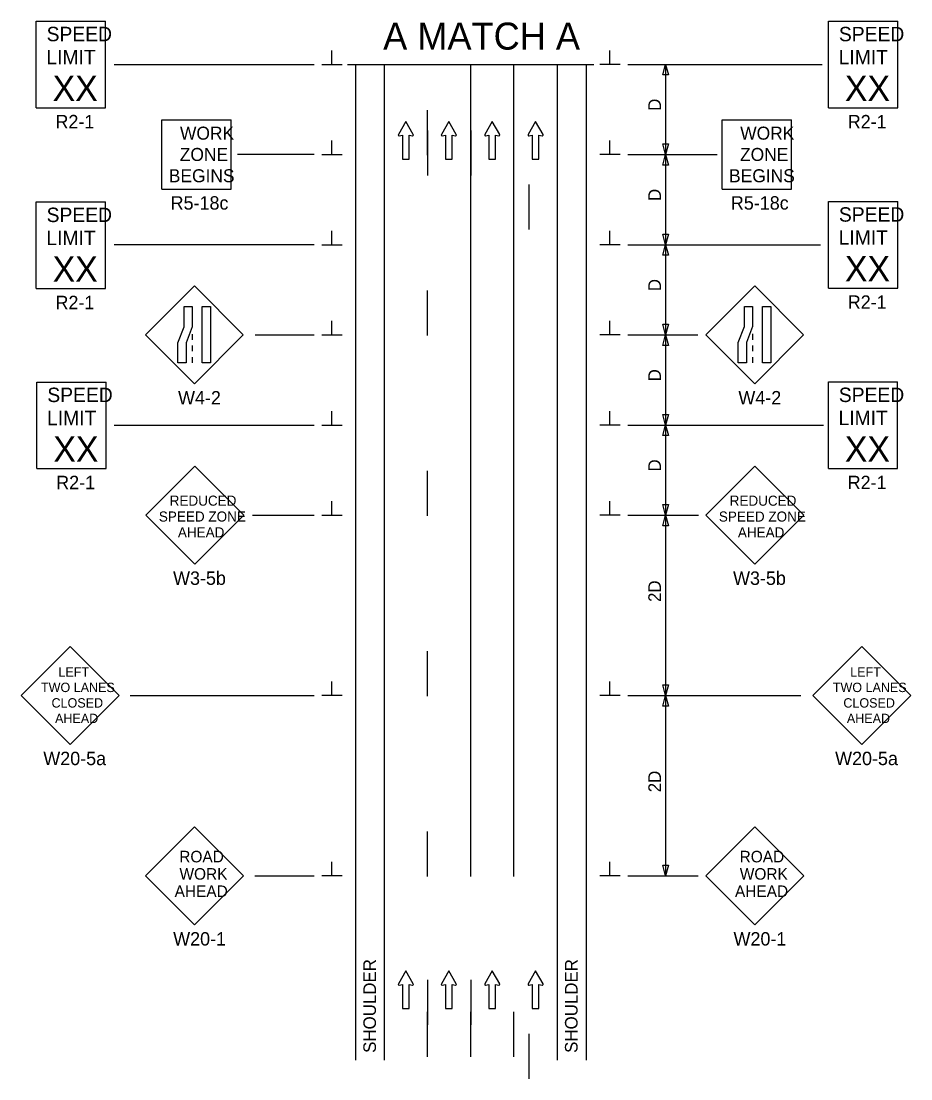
# Model space of a CAD drawing. Extents: x 16519 to 19508, y 5743 to 6974.
# Drawn here: x 17852 to 18345, y 6327 to 6913 of the extents above; entities that cross this region are included whole.
import ezdxf

# ---------------------------------------------------------------- set-up
doc = ezdxf.new("R2010")
doc.units = 0
for name, color, linetype in [('ALI_LEGAL_EX', 7, 'Continuous'), ('MT_SCRATCH_LEVEL_E', 7, 'Continuous'), ('PAVT_EDGE_EX', 7, 'Continuous'), ('TRAFFIC_SIGNS_PR', 7, 'Continuous'), ('TYPICAL_TEXT_DIMEN_PR', 7, 'Continuous')]:
    doc.layers.add(name, color=color, linetype=linetype)

msp = doc.modelspace()

# ---------------------------------------------------------------- linework, layer by layer
at = {"layer": 'ALI_LEGAL_EX'}
for p, q in [((18101.18, 6438.7), (18101.18, 6889.05)), ((18125.18, 6438.7), (18125.18, 6889.05))]:
    msp.add_line(p, q, dxfattribs=at)
for points in [[(18077.18, 6838.7), (18077.18, 6863.7)], [(18101.18, 6838.7), (18101.18, 6863.7)], [(18125.18, 6838.7), (18125.18, 6863.7)], [(18077.28, 6852.4), (18077.28, 6827.4)], [(18101.28, 6852.4), (18101.28, 6827.4)], [(18133.42, 6822.52), (18133.42, 6797.52)], [(18077.18, 6738.7), (18077.18, 6763.7)], [(18101.18, 6738.7), (18101.18, 6763.7)], [(18125.18, 6738.7), (18125.18, 6763.7)], [(18077.18, 6638.7), (18077.18, 6663.7)], [(18101.18, 6638.7), (18101.18, 6663.7)], [(18125.18, 6638.7), (18125.18, 6663.7)], [(18077.18, 6538.7), (18077.18, 6563.7)], [(18101.18, 6538.7), (18101.18, 6563.7)], [(18125.18, 6538.7), (18125.18, 6563.7)], [(18077.18, 6438.7), (18077.18, 6463.7)], [(18101.18, 6438.7), (18101.18, 6463.7)], [(18125.18, 6438.7), (18125.18, 6463.7)], [(18077.28, 6381.39), (18077.28, 6356.39)], [(18101.28, 6381.39), (18101.28, 6356.39)], [(18077.18, 6338.7), (18077.18, 6363.7)], [(18101.18, 6338.7), (18101.18, 6363.7)], [(18125.18, 6338.7), (18125.18, 6363.7)], [(18133.42, 6351.51), (18133.42, 6326.51)]]:
    msp.add_lwpolyline(points, dxfattribs=at)
at = {"layer": 'MT_SCRATCH_LEVEL_E'}
for p, q in [((18065.19, 6857.36), (18061.08, 6850.12)), ((18069.34, 6850.12), (18065.19, 6857.36)), ((18089.05, 6857.36), (18084.94, 6850.12)), ((18093.19, 6850.12), (18089.05, 6857.36)), ((18113.1, 6857.36), (18108.99, 6850.12)), ((18117.25, 6850.12), (18113.1, 6857.36)), ((18137.15, 6857.36), (18133.04, 6850.12)), ((18137.15, 6857.36), (18133.04, 6850.12)), ((18141.3, 6850.12), (18137.15, 6857.36)), ((18141.3, 6850.12), (18137.15, 6857.36)), ((18061.57, 6849.44), (18063.34, 6849.75)), ((18063.34, 6849.75), (18063.34, 6836.5)), ((18067.08, 6836.5), (18067.08, 6849.75)), ((18067.08, 6849.75), (18068.86, 6849.44)), ((18085.42, 6849.44), (18087.19, 6849.75)), ((18087.19, 6849.75), (18087.19, 6836.5)), ((18090.94, 6836.5), (18090.94, 6849.75)), ((18090.94, 6849.75), (18092.71, 6849.44)), ((18109.47, 6849.44), (18111.25, 6849.75)), ((18111.25, 6849.75), (18111.25, 6836.5)), ((18114.99, 6836.5), (18114.99, 6849.75)), ((18114.99, 6849.75), (18116.77, 6849.44)), ((18133.52, 6849.44), (18135.3, 6849.76)), ((18133.52, 6849.44), (18135.3, 6849.76)), ((18135.3, 6849.76), (18135.3, 6836.5)), ((18135.3, 6849.76), (18135.3, 6836.5)), ((18139.04, 6836.5), (18139.04, 6849.76)), ((18139.04, 6849.76), (18140.82, 6849.44)), ((18139.04, 6836.5), (18139.04, 6849.76)), ((18139.04, 6849.76), (18140.82, 6849.44)), ((18063.34, 6836.5), (18067.08, 6836.5)), ((18087.19, 6836.5), (18090.94, 6836.5)), ((18111.25, 6836.5), (18114.99, 6836.5)), ((18135.3, 6836.5), (18139.04, 6836.5)), ((18135.3, 6836.5), (18139.04, 6836.5)), ((18065.19, 6386.35), (18061.08, 6379.11)), ((18069.34, 6379.11), (18065.19, 6386.35)), ((18089.05, 6386.35), (18084.94, 6379.11)), ((18093.19, 6379.11), (18089.05, 6386.35)), ((18113.1, 6386.35), (18108.99, 6379.11)), ((18117.25, 6379.11), (18113.1, 6386.35)), ((18137.15, 6386.35), (18133.04, 6379.11)), ((18137.15, 6386.35), (18133.04, 6379.11)), ((18141.3, 6379.11), (18137.15, 6386.35)), ((18141.3, 6379.11), (18137.15, 6386.35)), ((18061.57, 6378.43), (18063.34, 6378.74)), ((18063.34, 6378.74), (18063.34, 6365.49)), ((18067.08, 6365.49), (18067.08, 6378.74)), ((18067.08, 6378.74), (18068.86, 6378.43)), ((18085.42, 6378.43), (18087.19, 6378.74)), ((18087.19, 6378.74), (18087.19, 6365.49)), ((18090.94, 6365.49), (18090.94, 6378.74)), ((18090.94, 6378.74), (18092.71, 6378.43)), ((18109.47, 6378.43), (18111.25, 6378.74)), ((18111.25, 6378.74), (18111.25, 6365.49)), ((18114.99, 6365.49), (18114.99, 6378.74)), ((18114.99, 6378.74), (18116.77, 6378.43)), ((18133.52, 6378.43), (18135.3, 6378.74)), ((18133.52, 6378.43), (18135.3, 6378.74)), ((18135.3, 6378.74), (18135.3, 6365.49)), ((18135.3, 6378.74), (18135.3, 6365.49)), ((18139.04, 6365.49), (18139.04, 6378.74)), ((18139.04, 6378.74), (18140.82, 6378.43)), ((18139.04, 6365.49), (18139.04, 6378.74)), ((18139.04, 6378.74), (18140.82, 6378.43)), ((18063.34, 6365.49), (18067.08, 6365.49)), ((18087.19, 6365.49), (18090.94, 6365.49)), ((18111.25, 6365.49), (18114.99, 6365.49)), ((18135.3, 6365.49), (18139.04, 6365.49)), ((18135.3, 6365.49), (18139.04, 6365.49))]:
    msp.add_line(p, q, dxfattribs=at)
for centre, start, end in [((18061.49, 6849.9), 150.42484, 279.96381), ((18068.93, 6849.9), 260.03619, 29.77312), ((18085.34, 6849.9), 150.42484, 279.96381), ((18092.78, 6849.9), 260.03619, 29.77312), ((18109.4, 6849.9), 150.42484, 279.96381), ((18116.84, 6849.9), 260.03619, 29.77312), ((18133.45, 6849.9), 150.42484, 279.96381), ((18133.45, 6849.9), 150.42484, 279.96381), ((18140.89, 6849.9), 260.03619, 29.77312), ((18140.89, 6849.9), 260.03619, 29.77312), ((18061.49, 6378.89), 150.42484, 279.96381), ((18068.93, 6378.89), 260.03619, 29.77312), ((18085.34, 6378.89), 150.42484, 279.96381), ((18092.78, 6378.89), 260.03619, 29.77312), ((18109.4, 6378.89), 150.42484, 279.96381), ((18116.84, 6378.89), 260.03619, 29.77312), ((18133.45, 6378.89), 150.42484, 279.96381), ((18133.45, 6378.89), 150.42484, 279.96381), ((18140.89, 6378.89), 260.03619, 29.77312), ((18140.89, 6378.89), 260.03619, 29.77312)]:
    msp.add_arc(centre, 0.463, start, end, dxfattribs=at)
at = {"layer": 'PAVT_EDGE_EX'}
for p, q in [((18037.18, 6889.05), (18037.18, 6336.88)), ((18053.18, 6889.05), (18053.18, 6336.88)), ((18149.18, 6889.05), (18149.18, 6336.88)), ((18165.18, 6889.05), (18165.18, 6336.88))]:
    msp.add_line(p, q, dxfattribs=at)
at = {"layer": 'TRAFFIC_SIGNS_PR'}
for p, q in [((17860.13, 6913.02), (17898.53, 6913.02)), ((17860.13, 6865.02), (17860.13, 6913.02)), ((17898.53, 6865.02), (17898.53, 6913.02)), ((18299.69, 6913), (18338.09, 6913)), ((18299.69, 6865), (18299.69, 6913)), ((18338.09, 6865), (18338.09, 6913)), ((17860.13, 6865.02), (17898.53, 6865.02)), ((18299.69, 6865), (18338.09, 6865)), ((17929.89, 6819.94), (17929.89, 6858.34)), ((17929.89, 6858.34), (17968.29, 6858.34)), ((17968.29, 6819.94), (17968.29, 6858.34)), ((18240.71, 6819.94), (18240.71, 6858.34)), ((18240.71, 6858.34), (18279.11, 6858.34)), ((18279.11, 6819.94), (18279.11, 6858.34)), ((17929.89, 6819.94), (17968.29, 6819.94)), ((18240.71, 6819.94), (18279.11, 6819.94)), ((17860.13, 6812.74), (17898.53, 6812.74)), ((17860.13, 6764.74), (17860.13, 6812.74)), ((17898.53, 6764.74), (17898.53, 6812.74)), ((18299.69, 6812.96), (18338.09, 6812.96)), ((18299.69, 6764.96), (18299.69, 6812.96)), ((18338.09, 6764.96), (18338.09, 6812.96)), ((17860.13, 6764.74), (17898.53, 6764.74)), ((17947.86, 6766.19), (17920.71, 6739.04)), ((17975.01, 6739.04), (17947.86, 6766.19)), ((18258.74, 6766.22), (18231.58, 6739.07)), ((18285.89, 6739.07), (18258.74, 6766.22)), ((18299.69, 6764.96), (18338.09, 6764.96)), ((17920.71, 6739.04), (17947.86, 6711.89)), ((17946.61, 6739.53), (17946.61, 6736.33)), ((17947.86, 6711.89), (17975.01, 6739.04)), ((18231.58, 6739.07), (18258.74, 6711.92)), ((18257.49, 6739.56), (18257.49, 6736.36)), ((18258.74, 6711.92), (18285.89, 6739.07)), ((18257.49, 6733.16), (18257.49, 6729.96)), ((17946.61, 6733.13), (17946.61, 6729.93)), ((17946.61, 6726.73), (17946.61, 6723.53)), ((18257.49, 6726.76), (18257.49, 6723.56)), ((17860.53, 6712.92), (17898.93, 6712.92)), ((17860.53, 6664.92), (17860.53, 6712.92)), ((17898.93, 6664.92), (17898.93, 6712.92)), ((18299.65, 6712.95), (18338.05, 6712.95)), ((18299.65, 6664.95), (18299.65, 6712.95)), ((18338.05, 6664.95), (18338.05, 6712.95)), ((17860.53, 6664.92), (17898.93, 6664.92)), ((17948.12, 6666.17), (17920.97, 6639.02)), ((17975.27, 6639.02), (17948.12, 6666.17)), ((18258.8, 6666.16), (18231.65, 6639.01)), ((18285.95, 6639.01), (18258.8, 6666.16)), ((18299.65, 6664.95), (18338.05, 6664.95)), ((17920.97, 6639.02), (17948.12, 6611.87)), ((17948.12, 6611.87), (17975.27, 6639.02)), ((18231.65, 6639.01), (18258.8, 6611.85)), ((18258.8, 6611.85), (18285.95, 6639.01)), ((17878.92, 6566.2), (17851.76, 6539.05)), ((17906.07, 6539.05), (17878.92, 6566.2)), ((18318.22, 6566.2), (18291.07, 6539.05)), ((18345.38, 6539.05), (18318.22, 6566.2)), ((17851.76, 6539.05), (17878.92, 6511.9)), ((17878.92, 6511.9), (17906.07, 6539.05)), ((18291.07, 6539.05), (18318.22, 6511.9)), ((18318.22, 6511.9), (18345.38, 6539.05)), ((17947.95, 6466.17), (17920.8, 6439.01)), ((17975.1, 6439.01), (17947.95, 6466.17)), ((18258.83, 6466.17), (18231.67, 6439.01)), ((18285.98, 6439.01), (18258.83, 6466.17)), ((17920.8, 6439.01), (17947.95, 6411.86)), ((17947.95, 6411.86), (17975.1, 6439.01)), ((18231.67, 6439.01), (18258.83, 6411.86)), ((18258.83, 6411.86), (18285.98, 6439.01))]:
    msp.add_line(p, q, dxfattribs=at)
for points in [[(17946.61, 6754.78), (17946.61, 6743.6), (17943.27, 6734.71), (17943.27, 6723.53), (17938.77, 6723.53), (17938.77, 6734.71), (17942.12, 6743.6), (17942.12, 6754.78)], [(17956.75, 6754.78), (17956.75, 6723.53), (17952.25, 6723.53), (17952.25, 6754.78)], [(18257.49, 6754.81), (18257.49, 6743.63), (18254.14, 6734.74), (18254.14, 6723.56), (18249.65, 6723.56), (18249.65, 6734.74), (18252.99, 6743.63), (18252.99, 6754.81)], [(18267.62, 6754.81), (18267.62, 6723.56), (18263.13, 6723.56), (18263.13, 6754.81)]]:
    msp.add_lwpolyline(points, close=True, dxfattribs=at)
at = {"layer": 'TYPICAL_TEXT_DIMEN_PR'}
for p, q in [((18024.15, 6889.05), (18024.15, 6896.83)), ((18178.4, 6889.05), (18178.4, 6896.83)), ((17903.38, 6889.05), (18014.28, 6889.05)), ((18018.53, 6889.05), (18029.78, 6889.05)), ((18032.85, 6889.05), (18169.5, 6889.05)), ((18184.03, 6889.05), (18172.78, 6889.05)), ((18188.28, 6889.05), (18296.09, 6889.05)), ((18207.71, 6883.19), (18209.28, 6889.05)), ((18209.28, 6889.05), (18209.28, 6839.05)), ((18209.28, 6889.05), (18210.85, 6883.19)), ((18209.28, 6883.19), (18207.71, 6883.19)), ((18210.85, 6883.19), (18209.28, 6883.19)), ((18024.15, 6839.05), (18024.15, 6846.83)), ((18178.4, 6839.05), (18178.4, 6846.83)), ((18209.28, 6839.05), (18207.71, 6844.91)), ((18207.71, 6844.91), (18209.28, 6844.91)), ((18209.28, 6844.91), (18210.85, 6844.91)), ((18210.85, 6844.91), (18209.28, 6839.05)), ((18014.28, 6839.05), (17971.89, 6839.05)), ((18018.53, 6839.05), (18029.78, 6839.05)), ((18184.03, 6839.05), (18172.78, 6839.05)), ((18188.28, 6839.05), (18237.93, 6839.05)), ((18207.71, 6833.19), (18209.28, 6839.05)), ((18209.28, 6839.05), (18210.85, 6833.19)), ((18209.28, 6839.05), (18209.28, 6789.05)), ((18209.28, 6833.19), (18207.71, 6833.19)), ((18210.85, 6833.19), (18209.28, 6833.19)), ((18024.15, 6789.05), (18024.15, 6796.83)), ((18178.4, 6789.05), (18178.4, 6796.83)), ((18209.28, 6789.05), (18207.71, 6794.91)), ((18207.71, 6794.91), (18209.28, 6794.91)), ((18209.28, 6794.91), (18210.85, 6794.91)), ((18210.85, 6794.91), (18209.28, 6789.05)), ((18014.28, 6789.05), (17903.38, 6789.05)), ((18018.53, 6789.05), (18029.78, 6789.05)), ((18184.03, 6789.05), (18172.78, 6789.05)), ((18188.28, 6789.05), (18295.2, 6789.05)), ((18207.71, 6783.19), (18209.28, 6789.05)), ((18209.28, 6789.05), (18209.28, 6739.05)), ((18209.28, 6789.05), (18210.85, 6783.19)), ((18209.28, 6783.19), (18207.71, 6783.19)), ((18210.85, 6783.19), (18209.28, 6783.19)), ((18024.15, 6739.05), (18024.15, 6746.83)), ((18178.4, 6739.05), (18178.4, 6746.83)), ((18209.28, 6739.05), (18207.71, 6744.91)), ((18207.71, 6744.91), (18209.28, 6744.91)), ((18209.28, 6744.91), (18210.85, 6744.91)), ((18210.85, 6744.91), (18209.28, 6739.05)), ((17981.56, 6739.05), (18014.28, 6739.05)), ((18018.53, 6739.05), (18029.78, 6739.05)), ((18184.03, 6739.05), (18172.78, 6739.05)), ((18188.28, 6739.05), (18227.24, 6739.05)), ((18207.71, 6733.19), (18209.28, 6739.05)), ((18209.28, 6739.05), (18209.28, 6689.05)), ((18209.28, 6739.05), (18210.85, 6733.19)), ((18209.28, 6733.19), (18207.71, 6733.19)), ((18210.85, 6733.19), (18209.28, 6733.19)), ((18024.15, 6689.05), (18024.15, 6696.83)), ((18178.4, 6689.05), (18178.4, 6696.83)), ((18209.28, 6689.05), (18207.71, 6694.91)), ((18207.71, 6694.91), (18209.28, 6694.91)), ((18209.28, 6694.91), (18210.85, 6694.91)), ((18210.85, 6694.91), (18209.28, 6689.05)), ((17903.38, 6689.05), (18014.28, 6689.05)), ((18018.53, 6689.05), (18029.78, 6689.05)), ((18184.03, 6689.05), (18172.78, 6689.05)), ((18188.28, 6689.05), (18296.94, 6689.05)), ((18207.71, 6683.19), (18209.28, 6689.05)), ((18209.28, 6689.05), (18209.28, 6639.05)), ((18209.28, 6689.05), (18210.85, 6683.19)), ((18209.28, 6683.19), (18207.71, 6683.19)), ((18210.85, 6683.19), (18209.28, 6683.19)), ((18024.15, 6639.05), (18024.15, 6646.83)), ((18178.4, 6639.05), (18178.4, 6646.83)), ((18209.28, 6639.05), (18207.71, 6644.91)), ((18207.71, 6644.91), (18209.28, 6644.91)), ((18209.28, 6644.91), (18210.85, 6644.91)), ((18210.85, 6644.91), (18209.28, 6639.05)), ((17980.17, 6639.05), (18014.28, 6639.05)), ((18018.53, 6639.05), (18029.78, 6639.05)), ((18184.03, 6639.05), (18172.78, 6639.05)), ((18188.28, 6639.05), (18227.55, 6639.05)), ((18207.71, 6633.19), (18209.28, 6639.05)), ((18207.71, 6633.19), (18209.28, 6639.05)), ((18209.28, 6639.05), (18209.28, 6539.05)), ((18209.28, 6639.05), (18210.85, 6633.19)), ((18209.28, 6639.05), (18210.85, 6633.19)), ((18209.28, 6639.05), (18209.28, 6539.05)), ((18209.28, 6633.19), (18207.71, 6633.19)), ((18209.28, 6633.19), (18207.71, 6633.19)), ((18210.85, 6633.19), (18209.28, 6633.19)), ((18210.85, 6633.19), (18209.28, 6633.19)), ((18024.15, 6539.05), (18024.15, 6546.83)), ((18024.15, 6539.05), (18024.15, 6546.83)), ((18178.4, 6539.05), (18178.4, 6546.83)), ((18178.4, 6539.05), (18178.4, 6546.83)), ((18209.28, 6539.05), (18207.71, 6544.91)), ((18207.71, 6544.91), (18209.28, 6544.91)), ((18209.28, 6544.91), (18210.85, 6544.91)), ((18210.85, 6544.91), (18209.28, 6539.05)), ((17912.26, 6539.05), (18014.28, 6539.05)), ((18029.78, 6539.05), (18018.53, 6539.05)), ((18029.78, 6539.05), (18018.53, 6539.05)), ((18184.03, 6539.05), (18172.78, 6539.05)), ((18184.03, 6539.05), (18172.78, 6539.05)), ((18188.28, 6539.05), (18284.37, 6539.05)), ((18188.28, 6539.05), (18214.28, 6539.05)), ((18207.71, 6533.19), (18209.28, 6539.05)), ((18209.28, 6539.05), (18209.28, 6439.05)), ((18209.28, 6539.05), (18210.85, 6533.19)), ((18209.28, 6533.19), (18207.71, 6533.19)), ((18210.85, 6533.19), (18209.28, 6533.19)), ((18024.15, 6439.05), (18024.15, 6446.83)), ((18178.4, 6439.05), (18178.4, 6446.83)), ((18209.28, 6439.05), (18207.71, 6444.91)), ((18207.71, 6444.91), (18209.28, 6444.91)), ((18209.28, 6444.91), (18210.85, 6444.91)), ((18210.85, 6444.91), (18209.28, 6439.05)), ((17981.38, 6439.05), (18014.28, 6439.05)), ((18029.78, 6439.05), (18018.53, 6439.05)), ((18184.03, 6439.05), (18172.78, 6439.05)), ((18188.28, 6439.05), (18227.41, 6439.05))]:
    msp.add_line(p, q, dxfattribs=at)

# ---------------------------------------------------------------- texts
at = {"layer": 'TRAFFIC_SIGNS_PR'}
for s, height, p in [('SPEED', 8, (17865.9, 6901.88)), ('SPEED', 8, (18305.46, 6901.86)), ('LIMIT', 8, (17865.74, 6889.08)), ('LIMIT', 8, (18305.3, 6889.06)), ('XX', 14.031, (17869.25, 6868.78)), ('XX', 14.031, (18308.8, 6868.75)), ('R2-1', 7.44, (17870.81, 6853.58)), ('R2-1', 7.44, (18310.37, 6853.56)), ('WORK', 7.217, (17939.89, 6847.3)), ('WORK', 7.217, (18250.71, 6847.3)), ('ZONE', 7.217, (17939.77, 6835.49)), ('ZONE', 7.217, (18250.59, 6835.49)), ('BEGINS', 7.217, (17933.7, 6823.68)), ('BEGINS', 7.217, (18244.52, 6823.68)), ('R5-18c', 7.44, (17934.7, 6808.5)), ('R5-18c', 7.44, (18245.52, 6808.5)), ('SPEED', 8, (17865.9, 6801.61)), ('SPEED', 8, (18305.46, 6801.83)), ('LIMIT', 8, (17865.74, 6788.81)), ('LIMIT', 8, (18305.3, 6789.03)), ('XX', 14.031, (17869.25, 6768.5)), ('XX', 14.031, (18308.8, 6768.72)), ('R2-1', 7.44, (17870.81, 6753.3)), ('R2-1', 7.44, (18310.37, 6753.52)), ('SPEED', 8, (17866.3, 6701.78)), ('SPEED', 8, (18305.42, 6701.81)), ('W4-2', 7.44, (17938.82, 6700.45)), ('W4-2', 7.44, (18249.69, 6700.48)), ('LIMIT', 8, (17866.14, 6688.98)), ('LIMIT', 8, (18305.26, 6689.01)), ('XX', 14.031, (17869.64, 6668.68)), ('XX', 14.031, (18308.77, 6668.71)), ('R2-1', 7.44, (17871.21, 6653.48)), ('R2-1', 7.44, (18310.33, 6653.51)), ('REDUCED', 5.6, (17934.18, 6644.33)), ('REDUCED', 5.6, (18244.86, 6644.31)), ('SPEED ZONE', 5.6, (17928.17, 6635.53)), ('SPEED ZONE', 5.6, (18238.85, 6635.51)), ('AHEAD', 5.6, (17938.73, 6626.73)), ('AHEAD', 5.6, (18249.41, 6626.71)), ('W3-5b', 7.44, (17936.07, 6600.43)), ('W3-5b', 7.44, (18246.75, 6600.41)), ('LEFT', 5.2, (17872.46, 6549.58)), ('LEFT', 5.2, (18311.76, 6549.58)), ('TWO LANES', 5.2, (17862.78, 6540.98)), ('TWO LANES', 5.2, (18302.09, 6540.98)), ('CLOSED', 5.2, (17868.63, 6532.38)), ('CLOSED', 5.2, (18307.94, 6532.38)), ('AHEAD', 5.2, (17870.58, 6523.78)), ('AHEAD', 5.2, (18309.88, 6523.78)), ('W20-5a', 7.44, (17864.06, 6500.46)), ('W20-5a', 7.44, (18303.36, 6500.46)), ('ROAD', 6.4, (17939.49, 6446.55)), ('ROAD', 6.4, (18250.37, 6446.55)), ('WORK', 6.4, (17939.6, 6436.95)), ('WORK', 6.4, (18250.48, 6436.95)), ('AHEAD', 6.4, (17936.91, 6427.35)), ('AHEAD', 6.4, (18247.79, 6427.35)), ('W20-1', 7.44, (17936.12, 6400.42)), ('W20-1', 7.44, (18247, 6400.42))]:
    msp.add_text(s, height=height, dxfattribs=at).set_placement(p)
at = {"layer": 'TYPICAL_TEXT_DIMEN_PR'}
msp.add_text('A MATCH A', height=15, dxfattribs=at).set_placement((18052.6, 6897.23))
for s, p in [('D', (18206.72, 6863.27)), ('D', (18206.72, 6813.27)), ('D', (18206.72, 6763.27)), ('D', (18206.72, 6713.27)), ('D', (18206.72, 6663.27)), ('2D', (18206.72, 6590.94)), ('2D', (18206.72, 6485.41)), ('SHOULDER', (18048.62, 6340.9)), ('SHOULDER', (18160.48, 6340.9))]:
    msp.add_text(s, height=7, rotation=90, dxfattribs=at).set_placement(p)

doc.saveas('drawing.dxf')
